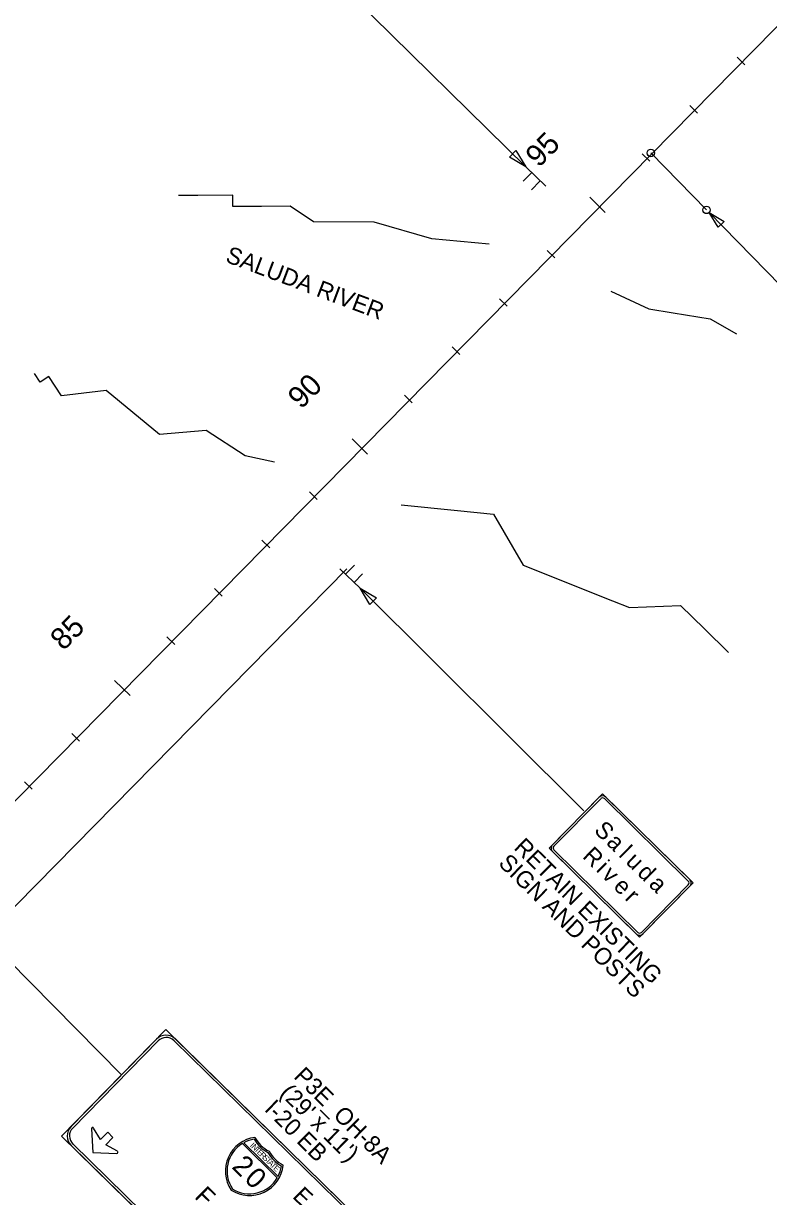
# Model space of a CAD drawing. Extents: x -5665 to 1997148, y 4 to 827579.
# Drawn here: x 1960479 to 1961578, y 796432 to 798163 of the extents above; entities that cross this region are included whole.
import ezdxf

# ---------------------------------------------------------------- set-up
doc = ezdxf.new("R2010")
doc.units = 0
for name, color, linetype in [('Default', 7, 'Continuous'), ('RD_HC_CL_Rel', 7, 'Continuous'), ('RD_HC_Data_Tic_Rel', 7, 'Continuous'), ('RD_HC_TX_Rel_Sta50', 7, 'Continuous'), ('RD_PD_Final_TX', 7, 'Continuous'), ('RD_SHT_ID', 7, 'Continuous'), ('RD_SHT_TX', 7, 'Continuous'), ('TR SN EXTRUDED PANEL SIGNS- MOUNTED OVERHEAD', 7, 'Continuous')]:
    doc.layers.add(name, color=color, linetype=linetype)

msp = doc.modelspace()

# ---------------------------------------------------------------- linework, layer by layer
at = {"layer": 'Default'}
msp.add_line((1960426.3, 796819.7), (1960955.8, 797357.9), dxfattribs=at)
at = {"layer": 'RD_HC_CL_Rel'}
msp.add_line((1957622, 794124.4), (1963740.1, 800343.8), dxfattribs=at)
at = {"layer": 'RD_HC_Data_Tic_Rel'}
for p, q in [((1961543.3, 798102), (1961531.9, 798113.3)), ((1961473.2, 798030.8), (1961461.7, 798042)), ((1961403, 797959.5), (1961391.6, 797970.7)), ((1961337.2, 797884), (1961314.4, 797906.4)), ((1961262.8, 797816.9), (1961251.4, 797828.1)), ((1961192.6, 797745.6), (1961181.2, 797756.8)), ((1961122.5, 797674.3), (1961111.1, 797685.5)), ((1961052.4, 797603), (1961041, 797614.2)), ((1960986.5, 797527.5), (1960963.7, 797550)), ((1960912.1, 797460.4), (1960900.7, 797471.7)), ((1960842, 797389.2), (1960830.6, 797400.4)), ((1960771.9, 797317.9), (1960760.5, 797329.1)), ((1960701.8, 797246.6), (1960690.3, 797257.8)), ((1960635.9, 797171.1), (1960613.1, 797193.5)), ((1960561.5, 797104), (1960550.1, 797115.2)), ((1960491.4, 797032.7), (1960480, 797043.9))]:
    msp.add_line(p, q, dxfattribs=at)
at = {"layer": 'RD_PD_Final_TX'}
for points in [[(1961195.6, 797965.7), (1961205.2, 797975.5), (1961220, 797951.2)], [(1960999.6, 797315.1), (1960989.9, 797305.3), (1960975.3, 797329.7)]]:
    msp.add_lwpolyline(points, close=True, dxfattribs=at)
at = {"layer": 'RD_SHT_ID'}
for points in [[(1961165.7, 797837.4), (1961123.4, 797841.3), (1961081.1, 797845.2), (1960996.3, 797869.9), (1960906.4, 797870.3), (1960872.3, 797893.3), (1960830, 797893), (1960787.7, 797892.6), (1960787.6, 797909.5), (1960735.8, 797909.1), (1960707.2, 797908.9)], [(1961345.1, 797768), (1961401.3, 797742), (1961401.3, 797742), (1961437.4, 797736), (1961492, 797726.8), (1961530.7, 797705)], [(1960849.1, 797515.5), (1960805.7, 797524.7), (1960748.2, 797562.3), (1960748.2, 797562.3), (1960679.5, 797556.5), (1960640.1, 797589), (1960600.7, 797621.5), (1960555.3, 797615.8), (1960534.7, 797613.2), (1960515.9, 797641.9), (1960503.2, 797633.6), (1960494.9, 797646.3), (1960494.9, 797646.3)], [(1961035.8, 797452.7), (1961119.1, 797444.1), (1961172, 797438.7), (1961216.1, 797363.5), (1961347.9, 797310.8), (1961373, 797300.8), (1961447.9, 797304.2), (1961483.4, 797269.4), (1961518.8, 797234.5), (1961518.8, 797234.5), (1961518.8, 797234.5)]]:
    msp.add_lwpolyline(points, dxfattribs=at)
at = {"layer": 'TR SN EXTRUDED PANEL SIGNS- MOUNTED OVERHEAD'}
for p, q in [((1961220, 797951.2), (1960874.7, 798291)), ((1961404.4, 797971.8), (1961486.5, 797887.8)), ((1961249.6, 797922.7), (1961220, 797951.2)), ((1961216.2, 797930.1), (1961228.6, 797943)), ((1961228.4, 797917.4), (1961240.8, 797930.3)), ((1961684.8, 797684.9), (1961490.5, 797883.9)), ((1960966.9, 797363.4), (1960954.5, 797350.6)), ((1960945.7, 797358.2), (1960975.3, 797329.7)), ((1960979.1, 797350.7), (1960966.7, 797337.9)), ((1961305.3, 797000.9), (1960975.3, 797329.7)), ((1960456.2, 796781.2), (1960623.5, 796611.4)), ((1960579.1, 796531.9), (1960581.1, 796496.6)), ((1960592.4, 796515.9), (1960582.2, 796532.9)), ((1960602.9, 796526.6), (1960592.4, 796515.9)), ((1960581.1, 796496.6), (1960616.4, 796495.3)), ((1960617.3, 796498.5), (1960600.1, 796508.3)), ((1960801.6, 796509.8), (1960853.2, 796459.3)), ((1960854.4, 796461.5), (1960803.9, 796511.1))]:
    msp.add_line(p, q, dxfattribs=at)
msp.add_lwpolyline([(1961512.5, 797870.9), (1961503.8, 797862.1), (1961490.5, 797883.9)], close=True, dxfattribs=at)
for points in [[(1961254.2, 796945.9), (1961387.8, 796814.4), (1961466.7, 796894.6), (1961333.1, 797026.1), (1961254.2, 796945.9), (1961254.2, 796945.9), (1961254.2, 796945.9)], [(1961259.1, 796950.9), (1961328.1, 797021.1)], [(1961330.4, 797018.9), (1961261.3, 796948.8)], [(1961330.4, 797018.9), (1961330.4, 797018.9), (1961330.4, 797018.9)], [(1961459.5, 796897.3), (1961335.9, 797019)], [(1961338.1, 797021.2), (1961461.7, 796899.6)], [(1961382.8, 796819.4), (1961259.2, 796941)], [(1961261.4, 796943.2), (1961385, 796821.6)], [(1961261.4, 796943.2), (1961261.4, 796943.2), (1961261.4, 796943.2)], [(1961459.5, 796897.3), (1961459.5, 796897.3), (1961459.5, 796897.3)], [(1961390.6, 796821.6), (1961459.6, 796891.8)], [(1961461.8, 796889.6), (1961392.8, 796819.5)], [(1961390.6, 796821.6), (1961390.6, 796821.6), (1961390.6, 796821.6)], [(1960534.9, 796520.9), (1960949.1, 796115), (1961103.1, 796272.1), (1960688.8, 796678.1), (1960534.9, 796520.9), (1960534.9, 796520.9)], [(1960548.9, 796535.2), (1960674.8, 796663.8)], [(1960677.2, 796661.4), (1960551.3, 796532.9)], [(1961086.5, 796283.8), (1960700.8, 796661.7)], [(1960703.1, 796664.1), (1961088.8, 796286.1)], [(1960579.1, 796531.9), (1960581.1, 796496.6), (1960581.1, 796496.6)], [(1960592.4, 796515.9), (1960582.2, 796532.9)], [(1960592.4, 796515.9), (1960602.9, 796526.6), (1960602.9, 796526.6)], [(1960602.9, 796526.6), (1960610.6, 796519), (1960600.1, 796508.3)], [(1960600.1, 796508.3), (1960610.6, 796519), (1960602.9, 796526.6)], [(1960934.9, 796129), (1960549.2, 796506.9)], [(1960551.5, 796509.3), (1960937.2, 796131.4)], [(1960581.1, 796496.6), (1960616.4, 796495.3)], [(1960617.3, 796498.5), (1960600.1, 796508.3)]]:
    msp.add_lwpolyline(points, dxfattribs=at)
for centre in [(1961404.4, 797971.8), (1961486.5, 797887.8)]:
    msp.add_circle(centre, 5.54, dxfattribs=at)
for centre, radius, start, end in [((1961333.2, 797016.2), 7.03, 45.4707, 135.4703), ((1961333.2, 797016.2), 3.91, 45.4707, 135.4703), ((1961264.1, 796946), 7.03, 135.4703, 225.4705), ((1961264.1, 796946), 3.91, 135.4703, 225.4705), ((1961456.8, 796894.6), 3.91, 315.4705, 45.4707), ((1961456.8, 796894.6), 7.03, 315.4705, 45.4707), ((1961387.8, 796824.4), 7.03, 225.4705, 315.4707), ((1961387.8, 796824.4), 3.91, 225.4705, 315.4707), ((1960689.1, 796649.8), 20, 45.5831, 135.5828), ((1960689.1, 796649.8), 16.7, 45.5831, 135.5828), ((1960563.2, 796521.2), 20, 135.5828, 225.583), ((1960563.2, 796521.2), 16.7, 135.5828, 225.583), ((1960580.7, 796532), 1.67, 31.1102, 182.5579), ((1960580.7, 796532), 1.67, 31.1102, 182.5579), ((1960826.5, 796469.4), 50, 97.2519, 214.0459), ((1960826.5, 796469.4), 50, 97.2519, 214.0459), ((1960826.5, 796469.4), 47.5, 99.2601, 118.5333), ((1960864, 796543.1), 52.5, 210.721, 241.9621), ((1960864.1, 796542.9), 50, 208.5919, 242.574), ((1960864.1, 796542.9), 50, 208.5919, 242.574), ((1960616.4, 796497), 1.67, 268.6081, 60.0557), ((1960616.4, 796497), 1.67, 268.6081, 60.0557), ((1960826.5, 796469.4), 47.5, 121.5986, 213.4454), ((1960885.2, 796522.4), 52.5, 209.2038, 240.4449), ((1960885, 796522.5), 50, 208.5919, 242.574), ((1960885, 796522.5), 50, 208.5919, 242.574), ((1960812.3, 796483.4), 50, 237.1201, 353.9141), ((1960812.3, 796483.4), 50, 237.1201, 353.9141), ((1960812.3, 796483.4), 47.5, 332.6324, 351.9057), ((1960812.2, 796483.3), 47.5, 237.7205, 329.5668)]:
    msp.add_arc(centre, radius, start, end, dxfattribs=at)

# ---------------------------------------------------------------- texts
at = {"layer": 'RD_HC_TX_Rel_Sta50'}
for s, p in [('95', (1961239.1, 797949.1)), ('90', (1960888.4, 797592.6)), ('85', (1960537.8, 797236.2))]:
    msp.add_text(s, height=32, rotation=45.4705, dxfattribs=at).set_placement(p)
at = {"layer": 'RD_SHT_TX'}
msp.add_text('SALUDA RIVER', height=25, rotation=339.371, dxfattribs=at).set_placement((1960775.2, 797811.6))
at = {"layer": 'TR SN EXTRUDED PANEL SIGNS- MOUNTED OVERHEAD'}
for s, height, rotation, p in [('S', 25, 315.4705, (1961319.2, 796970.8)), ('a', 25, 315.4705, (1961337.5, 796952.7)), ('RETAIN EXISTING', 25, 315.4705, (1961200.9, 796945.4)), ('R', 25, 315.4705, (1961302.2, 796932.6)), ('l', 25, 315.4705, (1961355.8, 796934.7)), ('SIGN AND POSTS', 25, 315.4705, (1961178.1, 796922.1)), ('i', 25, 315.4705, (1961322.4, 796912.8)), ('u', 25, 315.4705, (1961366, 796924.7)), ('v', 25, 315.4705, (1961330.8, 796904.5)), ('d', 25, 315.4705, (1961383.1, 796907.9)), ('e', 25, 315.4705, (1961347.8, 796887.8)), ('a', 25, 315.4705, (1961400.1, 796891.1)), ('r', 25, 315.4705, (1961364.9, 796870.9)), ('P3E_OH-8A', 25, 315.3323, (1960876.2, 796607.7)), ("(29' x 11')", 25, 315.3323, (1960855.6, 796582.6)), ('I-20 EB', 25, 315.3323, (1960832.7, 796559.4)), ('I', 8.33, 315.5829, (1960812.3, 796506.3)), ('N', 8.33, 315.5829, (1960814.4, 796504.3)), ('T', 8.33, 315.5829, (1960818.7, 796500.1)), ('E', 8.33, 315.5829, (1960822.6, 796496.2)), ('R', 8.33, 315.5829, (1960826.6, 796492.3)), ('2', 30, 315.5829, (1960784.7, 796474.5)), ('S', 8.33, 315.5829, (1960830.9, 796488.1)), ('T', 8.33, 315.5829, (1960835.1, 796484)), ('A', 8.33, 315.5829, (1960838.5, 796480.7)), ('T', 8.33, 315.5829, (1960842.5, 796476.7)), ('E', 8.33, 315.5829, (1960846.5, 796472.8)), ('0', 30, 315.5829, (1960803.1, 796456.4)), ('0', 30, 315.5829, (1960803.1, 796456.4)), ('F', 26.7, 315.5829, (1960729.8, 796430.3)), ('E', 25, 315.5829, (1960874.5, 796430.8))]:
    msp.add_text(s, height=height, rotation=rotation, dxfattribs=at).set_placement(p)

doc.saveas('drawing.dxf')
